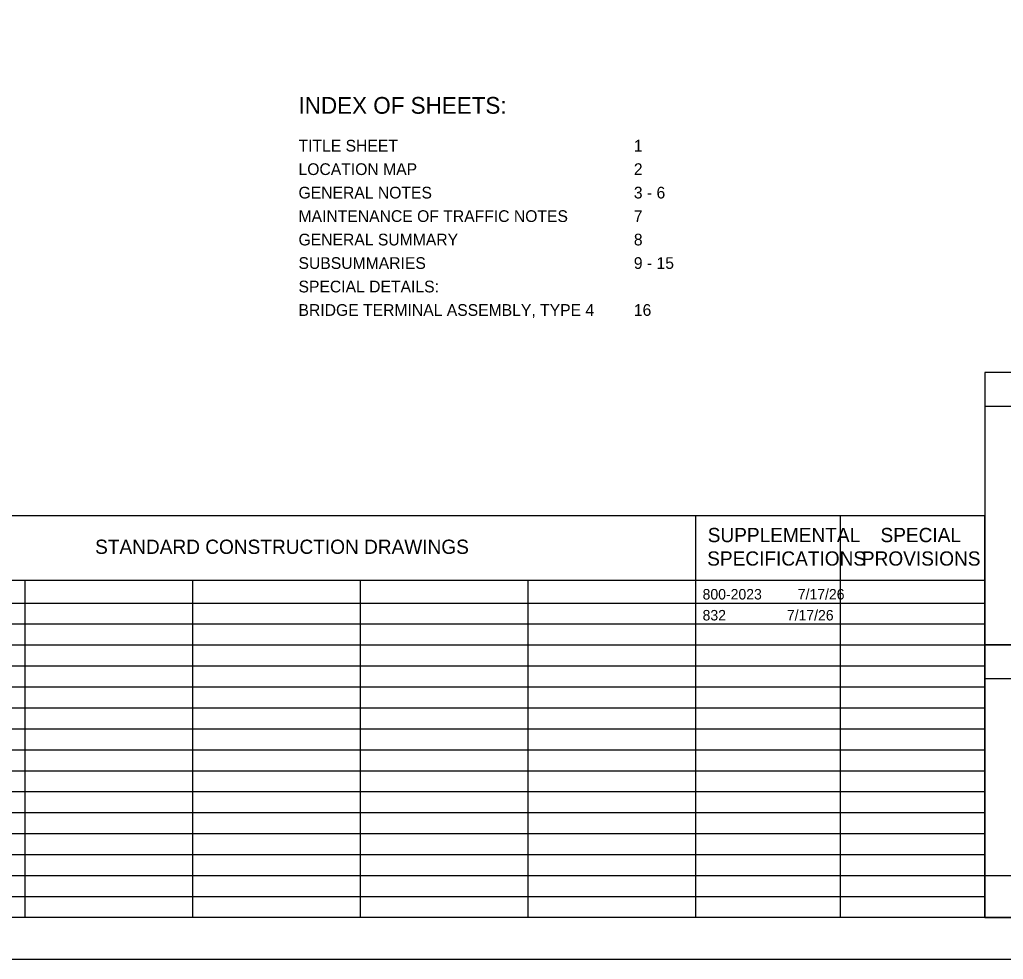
# Model space of a CAD drawing. Extents: x 0 to 34, y 0 to 22.
# Drawn here: x 12.09 to 23.82, y 0 to 11.21 of the extents above; entities that cross this region are included whole.
import ezdxf

# ---------------------------------------------------------------- set-up
doc = ezdxf.new("R2010")
doc.units = 0
for name, color, linetype in [('Default', 7, 'Continuous'), ('SH_Border', 7, 'Continuous'), ('SH_Cut_Line', 7, 'Continuous'), ('SH_Data', 7, 'Continuous'), ('SH_Text', 7, 'Continuous')]:
    doc.layers.add(name, color=color, linetype=linetype)

msp = doc.modelspace()

# ---------------------------------------------------------------- linework, layer by layer
at = {"layer": 'SH_Border'}
msp.add_lwpolyline([(1.5, 21.5), (33.5, 21.5), (33.5, 0.5), (1.5, 0.5)], close=True, dxfattribs=at)
at = {"layer": 'SH_Cut_Line'}
msp.add_lwpolyline([(0, 0), (34, 0), (34, 22), (0, 22)], close=True, dxfattribs=at)
at = {"layer": 'SH_Data'}
for p, q in [((23.6, 6.6), (26.4, 6.6)), ((10.15, 5.292), (23.6, 5.292)), ((20.15, 0.5), (20.15, 5.292)), ((21.875, 0.5), (21.875, 5.292)), ((23.6, 0.5), (23.6, 5.292)), ((10.15, 4.521), (23.6, 4.521)), ((12.15, 0.5), (12.15, 4.521)), ((14.15, 0.5), (14.15, 4.521)), ((16.15, 0.5), (16.15, 4.521)), ((18.15, 0.5), (18.15, 4.521)), ((10.15, 4.25), (23.6, 4.25)), ((10.15, 4), (23.6, 4)), ((10.15, 3.75), (23.6, 3.75)), ((23.6, 0.5), (23.6, 3.75)), ((23.6, 3.75), (26.4, 3.75)), ((10.15, 3.5), (23.6, 3.5)), ((23.6, 3.35), (26.4, 3.35)), ((23.6, 3.35), (26.4, 3.35)), ((10.15, 3.25), (23.6, 3.25)), ((10.15, 3), (23.6, 3)), ((10.15, 2.75), (23.6, 2.75)), ((10.15, 2.5), (23.6, 2.5)), ((10.15, 2.25), (23.6, 2.25)), ((10.15, 2), (23.6, 2)), ((10.15, 1.75), (23.6, 1.75)), ((10.15, 1.5), (23.6, 1.5)), ((10.15, 1.25), (23.6, 1.25)), ((10.15, 1), (23.6, 1)), ((10.15, 0.75), (23.6, 0.75)), ((23.6, 0.5), (26.4, 0.5))]:
    msp.add_line(p, q, dxfattribs=at)
for points in [[(26.4, 7), (23.6, 7), (23.6, 3.75), (26.4, 3.75)], [(26.4, 3.75), (23.6, 3.75), (23.6, 0.5), (26.4, 0.5)], [(23.6, 0.5), (23.6, 1), (26.4, 1), (26.4, 0.5)]]:
    msp.add_lwpolyline(points, close=True, dxfattribs=at)

# ---------------------------------------------------------------- texts
at = {"layer": 'Default'}
for s, p in [('800-2023', (20.232, 4.292)), ('7/17/26', (21.367, 4.292)), ('832', (20.232, 4.042)), ('7/17/26', (21.237, 4.042))]:
    msp.add_text(s, height=0.125, dxfattribs=at).set_placement(p)
at = {"layer": 'SH_Text'}
for s, height, p in [('INDEX OF SHEETS:', 0.2, (15.412, 10.086)), ('TITLE SHEET', 0.14, (15.412, 9.635)), ('1', 0.14, (19.412, 9.635)), ('LOCATION MAP', 0.14, (15.412, 9.355)), ('2', 0.14, (19.412, 9.355)), ('GENERAL NOTES', 0.14, (15.412, 9.075)), ('3 - 6', 0.14, (19.412, 9.075)), ('MAINTENANCE OF TRAFFIC NOTES', 0.14, (15.412, 8.795)), ('7', 0.14, (19.412, 8.795)), ('GENERAL SUMMARY', 0.14, (15.412, 8.515)), ('8', 0.14, (19.412, 8.515)), ('SUBSUMMARIES', 0.14, (15.412, 8.235)), ('9 - 15', 0.14, (19.412, 8.235)), ('SPECIAL DETAILS:', 0.14, (15.412, 7.955)), ('BRIDGE TERMINAL ASSEMBLY, TYPE 4', 0.14, (15.412, 7.675)), ('16', 0.14, (19.412, 7.675)), ('SUPPLEMENTAL', 0.17, (20.293, 4.976)), ('SPECIAL', 0.17, (22.354, 4.976)), ('STANDARD CONSTRUCTION DRAWINGS', 0.17, (12.986, 4.836)), ('SPECIFICATIONS', 0.17, (20.287, 4.696)), ('PROVISIONS', 0.17, (22.132, 4.696))]:
    msp.add_text(s, height=height, dxfattribs=at).set_placement(p)

doc.saveas('drawing.dxf')
